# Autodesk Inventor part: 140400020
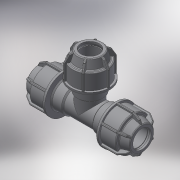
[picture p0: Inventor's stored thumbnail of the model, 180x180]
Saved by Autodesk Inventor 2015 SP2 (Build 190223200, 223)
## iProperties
Created: 2017-08
Part Number: 140400020
Material: Generic
Description: PLASSON L.14 TEE (SILVER) 20-20-20
Document SubType Name: Modeling
Designer: KIM
Density: 1 g/cm^3
Appearance: Default
Author: KIM
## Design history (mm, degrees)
derived "140400.ipt"
feature "Solid1::140400.ipt"
tag "TaggingFeature1"
body "Solid1"
other parameters: "d2" = 43, "d4" = 15 deg, "d5" = 28.38, "d6" = 9.3654, "d10" = 42, "d16" = 20.4, "d17" = 2.15, "d22" = 28, "d24" = 2.15, "d25" = 37.8, "d26" = 31.5, "d27" = 2.15, "d28" = 135 deg, "d29" = 1.29, "d31" = 1, "d46" = 150 deg, "d49" = 2.1, "d50" = 0, "d58" = 0.6, "d61" = 360 deg, "d63" = 18, "d64" = 56.5, "d78" = 180 deg, "d80" = 25.2, "d81" = 1.4, "d84" = 2.15, "d86" = 0, "d88" = 0, "d90" = 0, "d92" = 180 deg, "G_" = 18.631, "E_" = 42, "H_" = 113, "l_" = 43, "l_2" = 19
